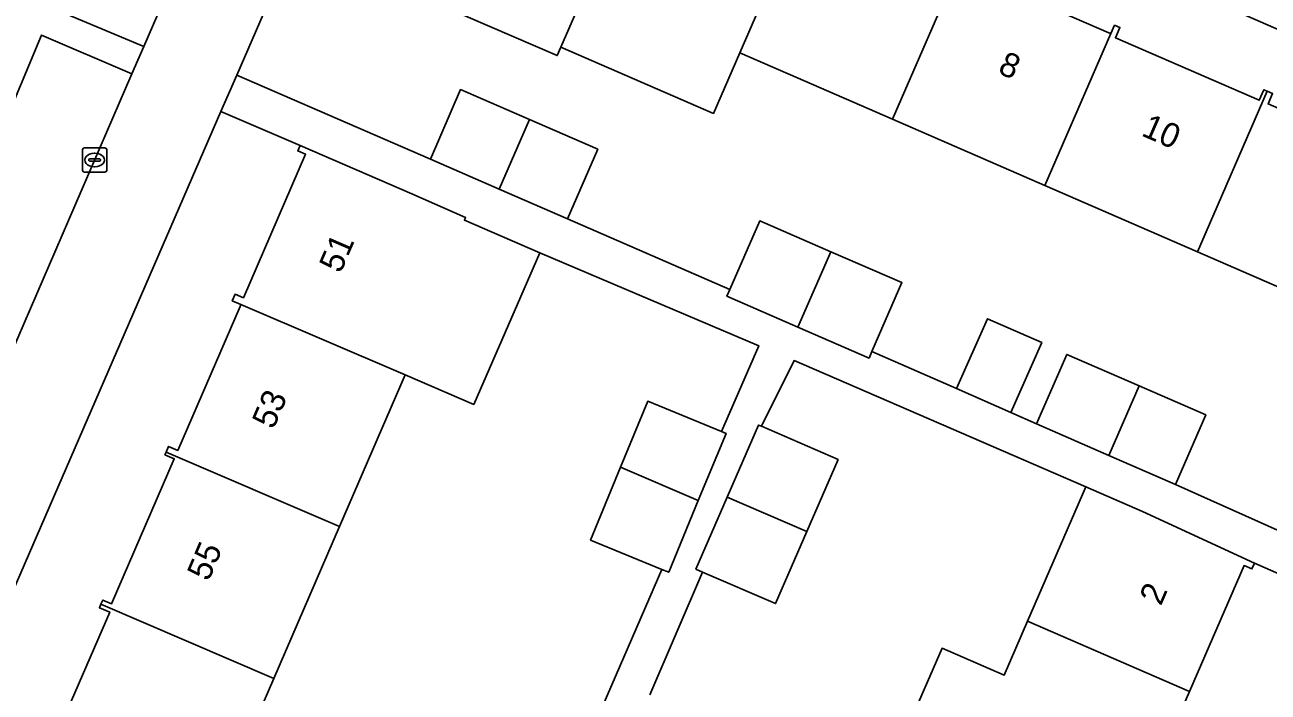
# Model space of a CAD drawing. Extents: x 162803 to 163818, y 381639 to 382475.
# Drawn here: x 163425.9 to 163477, y 381899.8 to 381927.2 of the extents above; entities that cross this region are included whole.
import ezdxf

# ---------------------------------------------------------------- set-up
doc = ezdxf.new("R2010")
doc.units = 0
for name, color, linetype in [('IMGEO_Berm_groen', 7, 'Continuous'), ('IMGEO_Erf', 7, 'Continuous'), ('IMGEO_Kolk', 7, 'Continuous'), ('IMGEO_Pand', 7, 'Continuous'), ('IMGEO_Pand_nummerreeks', 7, 'Continuous'), ('IMGEO_Voetpad_open', 7, 'Continuous')]:
    doc.layers.add(name, color=color, linetype=linetype)

msp = doc.modelspace()

# ---------------------------------------------------------------- linework, layer by layer
at = {"layer": 'IMGEO_Berm_groen'}
msp.add_lwpolyline([(163431.316, 381943.902), (163429.894, 381940.604), (163430.216, 381936.107), (163429.958, 381934.59), (163427.092, 381927.892), (163430.782, 381926.338), (163438.452, 381944.062)], dxfattribs=at)
msp.add_lwpolyline([(163430.297, 381925.219), (163426.581, 381926.812), (163424.833, 381922.667), (163422.867, 381918.772), (163420.305, 381915.765), (163418.016, 381910.493), (163422.983, 381908.314)], close=True, dxfattribs=at)
at = {"layer": 'IMGEO_Erf'}
for points in [[(163484.415, 381924), (163446.469, 381940.527), (163442.096, 381942.431), (163434.604, 381925.154), (163442.568, 381921.71), (163443.812, 381924.566), (163446.642, 381923.333), (163449.449, 381922.109), (163448.205, 381919.253), (163454.882, 381916.337), (163456.111, 381919.165), (163459.034, 381917.895), (163461.956, 381916.624), (163460.722, 381913.785), (163464.205, 381912.264), (163465.472, 381915.138), (163467.704, 381914.155), (163466.437, 381911.28), (163467.494, 381910.814), (163468.738, 381913.669), (163471.707, 381912.375), (163474.449, 381911.18), (163473.205, 381908.325), (163480.407, 381905.096)], [(163464.478, 381929.513), (163470.47, 381926.908), (163470.553, 381926.872), (163470.703, 381927.216), (163470.92, 381927.122), (163470.737, 381926.701), (163476.648, 381924.131), (163476.835, 381924.563), (163476.98, 381924.5), (163477.199, 381924.404), (163477.012, 381923.974), (163482.943, 381921.395)], [(163480.541, 381915.099), (163474.108, 381917.896), (163467.836, 381920.623), (163461.565, 381923.349), (163455.292, 381926.076), (163454.209, 381923.585), (163447.937, 381926.312), (163447.785, 381925.962), (163441.356, 381928.756)], [(163426.824, 381897.152), (163429.384, 381903.069), (163428.963, 381903.251), (163429.024, 381903.392), (163429.097, 381903.562), (163429.452, 381903.408), (163432.035, 381909.377), (163431.654, 381909.542), (163431.699, 381909.645), (163431.802, 381909.885), (163432.182, 381909.721), (163434.746, 381915.646), (163434.779, 381915.722), (163434.421, 381915.876), (163434.538, 381916.147), (163434.879, 381915.999), (163437.434, 381921.903), (163437.115, 381922.041), (163437.211, 381922.263), (163433.958, 381923.664), (163403.547, 381853.528)], [(163462.177, 381898.274), (163463.612, 381901.585), (163466.163, 381900.479), (163467.122, 381902.692), (163469.517, 381908.217), (163457.52, 381913.416), (163456.182, 381910.713), (163459.334, 381909.347), (163458.049, 381906.382), (163456.764, 381903.418), (163453.763, 381904.719), (163451.587, 381899.671)]]:
    msp.add_lwpolyline(points, dxfattribs=at)
for points in [[(163452.083, 381904.825), (163449.155, 381906.03), (163450.39, 381909.027), (163451.509, 381911.746), (163454.537, 381910.499), (163456.072, 381914.031), (163447.07, 381917.85), (163444.354, 381911.616), (163441.532, 381912.826), (163438.833, 381906.585), (163436.133, 381900.344), (163433.433, 381894.102), (163436.289, 381892.877), (163433.536, 381886.617), (163442.515, 381882.733), (163446.654, 381892.354), (163443.758, 381893.546), (163444.993, 381896.545), (163446.112, 381899.262), (163449.137, 381898.016)], [(163479.77, 381903.625), (163476.457, 381905.086), (163476.35, 381904.843), (163476.029, 381904.985), (163473.779, 381899.806), (163471.381, 381894.284), (163468.981, 381888.761), (163466.582, 381883.238), (163464.183, 381877.716), (163461.785, 381872.194), (163459.386, 381866.672), (163456.986, 381861.148), (163454.588, 381855.626), (163452.208, 381850.148), (163452.502, 381850.014), (163452.411, 381849.78), (163454.888, 381848.734), (163455.817, 381848.343)]]:
    msp.add_lwpolyline(points, close=True, dxfattribs=at)
at = {"layer": 'IMGEO_Kolk'}
for p, q in [((163428.262, 381921.244), (163428.262, 381922.096)), ((163428.337, 381922.17), (163429.189, 381922.17)), ((163428.521, 381921.664), (163428.521, 381921.676)), ((163428.564, 381921.713), (163428.962, 381921.713)), ((163428.75, 381921.95), (163428.775, 381921.95)), ((163429.005, 381921.676), (163429.005, 381921.664)), ((163429.263, 381922.096), (163429.263, 381921.244)), ((163429.189, 381921.17), (163428.337, 381921.17)), ((163428.959, 381921.627), (163428.561, 381921.627)), ((163428.773, 381921.39), (163428.748, 381921.39))]:
    msp.add_line(p, q, dxfattribs=at)
for points in [[(163428.262, 381921.244), (163428.262, 381922.096)], [(163428.337, 381922.17), (163429.189, 381922.17)], [(163429.263, 381922.096), (163429.263, 381921.244)], [(163429.189, 381921.17), (163428.337, 381921.17)]]:
    msp.add_lwpolyline(points, dxfattribs=at)
for centre, radius, start, end in [((163428.339, 381922.094), 0.0765, 91.552, 178.448), ((163428.339, 381922.094), 0.0765, 91.552, 178.448), ((163428.561, 381921.673), 0.0403, 85.8775, 175.7526), ((163428.966, 381921.675), 0.0386, 1.7309, 96.639), ((163429.187, 381922.094), 0.0765, 1.552, 88.448), ((163429.187, 381922.094), 0.0765, 1.552, 88.448), ((163428.339, 381921.246), 0.0765, 181.552, 268.448), ((163428.339, 381921.246), 0.0765, 181.552, 268.448), ((163428.558, 381921.663), 0.0366, 178.938, 274.7102), ((163428.962, 381921.67), 0.043, 264.8664, 352.4533), ((163429.187, 381921.246), 0.0765, 271.552, 358.448), ((163429.187, 381921.246), 0.0765, 271.552, 358.448)]:
    msp.add_arc(centre, radius, start, end, dxfattribs=at)
for centre, major_axis, ratio, start_param, end_param in [((163428.749, 381921.67), (-0.387, 0.002), 0.722429, 4.712389, 7.853982), ((163428.774, 381921.67), (-0.39, 0.002), 0.717154, 1.570796, 4.712389)]:
    msp.add_ellipse(centre, major_axis=major_axis, ratio=ratio, start_param=start_param, end_param=end_param, dxfattribs=at)
at = {"layer": 'IMGEO_Pand'}
for points in [[(163451.893, 381935.411), (163451.779, 381935.461), (163451.602, 381935.054), (163445.481, 381937.715), (163445.66, 381938.125), (163445.467, 381938.209), (163442.592, 381931.598), (163441.356, 381928.756), (163447.785, 381925.962), (163447.937, 381926.312), (163449.02, 381928.803)], [(163458.161, 381932.673), (163458.047, 381932.723), (163457.886, 381932.354), (163451.895, 381934.959), (163452.06, 381935.339), (163451.893, 381935.411), (163449.02, 381928.803), (163447.937, 381926.312), (163454.209, 381923.585), (163455.292, 381926.076)], [(163455.292, 381926.076), (163461.565, 381923.349), (163464.433, 381929.946), (163464.318, 381929.996), (163464.13, 381929.564), (163458.105, 381932.184), (163458.293, 381932.616), (163458.161, 381932.673)], [(163470.553, 381926.872), (163470.47, 381926.908), (163464.478, 381929.513), (163464.629, 381929.861), (163464.433, 381929.946), (163461.565, 381923.349), (163467.836, 381920.623)], [(163470.737, 381926.701), (163470.92, 381927.122), (163470.703, 381927.216), (163470.553, 381926.872), (163467.836, 381920.623), (163474.108, 381917.896), (163476.98, 381924.5), (163476.835, 381924.563), (163476.648, 381924.131)], [(163446.642, 381923.333), (163443.812, 381924.566), (163442.568, 381921.71), (163445.4, 381920.476)], [(163476.98, 381924.5), (163474.108, 381917.896), (163480.541, 381915.099), (163483.414, 381921.707), (163483.132, 381921.829), (163482.943, 381921.395), (163477.012, 381923.974), (163477.199, 381924.404)], [(163446.642, 381923.333), (163445.4, 381920.476), (163448.205, 381919.253), (163449.449, 381922.109)], [(163447.07, 381917.85), (163443.971, 381919.2), (163444.015, 381919.301), (163441.801, 381920.277), (163437.211, 381922.263), (163437.115, 381922.041), (163437.434, 381921.903), (163434.879, 381915.999), (163434.538, 381916.147), (163434.421, 381915.876), (163434.779, 381915.722), (163441.532, 381912.826), (163444.354, 381911.616)], [(163459.034, 381917.895), (163456.111, 381919.165), (163454.882, 381916.337), (163454.762, 381916.061), (163457.684, 381914.791)], [(163459.034, 381917.895), (163457.684, 381914.791), (163460.607, 381913.52), (163460.722, 381913.785), (163461.956, 381916.624)], [(163441.532, 381912.826), (163434.779, 381915.722), (163434.746, 381915.646), (163432.182, 381909.721), (163431.802, 381909.885), (163431.699, 381909.645), (163438.833, 381906.585)], [(163467.704, 381914.155), (163465.472, 381915.138), (163464.205, 381912.264), (163466.437, 381911.28)], [(163471.707, 381912.375), (163468.738, 381913.669), (163467.494, 381910.814), (163470.465, 381909.519)], [(163471.707, 381912.375), (163470.465, 381909.519), (163473.205, 381908.325), (163474.449, 381911.18)], [(163454.725, 381910.421), (163454.537, 381910.499), (163451.509, 381911.746), (163450.39, 381909.027), (163453.586, 381907.656)], [(163456.182, 381910.713), (163456.061, 381910.766), (163454.775, 381907.802), (163458.049, 381906.382), (163459.334, 381909.347)], [(163431.699, 381909.645), (163431.654, 381909.542), (163432.035, 381909.377), (163429.452, 381903.408), (163429.097, 381903.562), (163429.024, 381903.392), (163436.133, 381900.344), (163438.833, 381906.585)], [(163453.586, 381907.656), (163450.39, 381909.027), (163449.155, 381906.03), (163452.083, 381904.825), (163452.371, 381904.706)], [(163473.779, 381899.806), (163476.029, 381904.985), (163476.35, 381904.843), (163476.457, 381905.086), (163471.843, 381907.209), (163469.517, 381908.217), (163467.122, 381902.692)], [(163458.049, 381906.382), (163454.775, 381907.802), (163453.49, 381904.837), (163453.763, 381904.719), (163456.764, 381903.418)], [(163429.024, 381903.392), (163428.963, 381903.251), (163429.384, 381903.069), (163426.824, 381897.152), (163426.558, 381897.267), (163426.479, 381897.084), (163433.433, 381894.102), (163436.133, 381900.344)], [(163473.779, 381899.806), (163467.122, 381902.692), (163466.163, 381900.479), (163463.612, 381901.585), (163462.177, 381898.274), (163464.727, 381897.168), (163471.381, 381894.284)]]:
    msp.add_lwpolyline(points, close=True, dxfattribs=at)
at = {"layer": 'IMGEO_Voetpad_open'}
for points in [[(163448.434, 381942.962), (163444.86, 381944.518), (163443.345, 381945.184), (163442.096, 381942.431), (163446.469, 381940.527), (163484.415, 381924), (163485.599, 381923.488), (163486.278, 381922.892), (163486.823, 381922.171), (163487.284, 381925.897)], [(163433.958, 381923.664), (163434.604, 381925.154), (163442.096, 381942.431), (163438.452, 381944.062), (163430.782, 381926.338), (163430.297, 381925.219), (163422.983, 381908.314), (163422.504, 381907.226), (163416.497, 381893.39), (163415.281, 381890.601), (163414.692, 381889.232), (163409.552, 381877.287), (163409.054, 381876.142), (163400.375, 381856.069), (163399.544, 381854.142), (163392.292, 381837.534), (163395.819, 381835.705), (163403.019, 381852.311), (163403.547, 381853.528)]]:
    msp.add_lwpolyline(points, close=True, dxfattribs=at)
for points in [[(163424.833, 381922.667), (163426.581, 381926.812), (163430.297, 381925.219), (163430.782, 381926.338), (163427.092, 381927.892)], [(163480.407, 381905.096), (163473.205, 381908.325), (163470.465, 381909.519), (163467.494, 381910.814), (163466.437, 381911.28), (163464.205, 381912.264), (163460.722, 381913.785), (163460.607, 381913.52), (163457.684, 381914.791), (163454.762, 381916.061), (163454.882, 381916.337), (163448.205, 381919.253), (163445.4, 381920.476), (163442.568, 381921.71), (163434.604, 381925.154), (163433.958, 381923.664), (163437.211, 381922.263), (163441.801, 381920.277), (163444.015, 381919.301), (163443.971, 381919.2), (163447.07, 381917.85), (163456.072, 381914.031), (163454.537, 381910.499), (163454.725, 381910.421), (163453.586, 381907.656), (163452.371, 381904.706), (163452.083, 381904.825), (163449.137, 381898.016)], [(163451.587, 381899.671), (163453.763, 381904.719), (163453.49, 381904.837), (163454.775, 381907.802), (163456.061, 381910.766), (163456.182, 381910.713), (163457.52, 381913.416), (163469.517, 381908.217), (163471.843, 381907.209), (163476.457, 381905.086), (163479.77, 381903.625)]]:
    msp.add_lwpolyline(points, dxfattribs=at)

# ---------------------------------------------------------------- texts
at = {"layer": 'IMGEO_Pand_nummerreeks'}
for s, rotation, p in [('8', 336.4629, (163465.86, 381925.26)), ('10', 336.4629, (163471.759, 381922.689)), ('51', 66.6006, (163438.873, 381916.971)), ('53', 66.8584, (163436.117, 381910.554)), ('55', 66.8599, (163433.445, 381904.301)), ('2', 66.562, (163472.606, 381903.295))]:
    msp.add_text(s, height=1, rotation=rotation, dxfattribs=at).set_placement(p)

doc.saveas('drawing.dxf')
